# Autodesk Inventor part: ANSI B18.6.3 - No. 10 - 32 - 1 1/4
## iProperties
Shininess: 64.0
Length Units: 11272
Angle Units: 11279
Time Units: 11290
Mass Units: 11286
Length Display Precision: 3
Angle Display Precision: 2
Created: 2005-01
Part Number: ANSI B18.6.3 - No. 10 - 32 - 1 1/4
Vendor: Autodesk Inc.
Document SubType Name: Modeling
Designer: John Blackburn
Material: Default
Description: Slotted Truss Head Machine Screw
Standard: ANSI B18.6.3
Density: 0.0
Volumn: 0.0
Area: 0.0
PropertySet Name: Model Information
Control State: 0
Master: False
Checked Out: False
EGR: 4
Classification: un/spsc 31161504
Author: John Blackburn
Revision Number: 8
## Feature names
1. Body [Revolution]
2. Slot [Extrusion]
3. Fillet [Revolution]
